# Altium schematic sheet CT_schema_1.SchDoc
size 451 x 258 mm
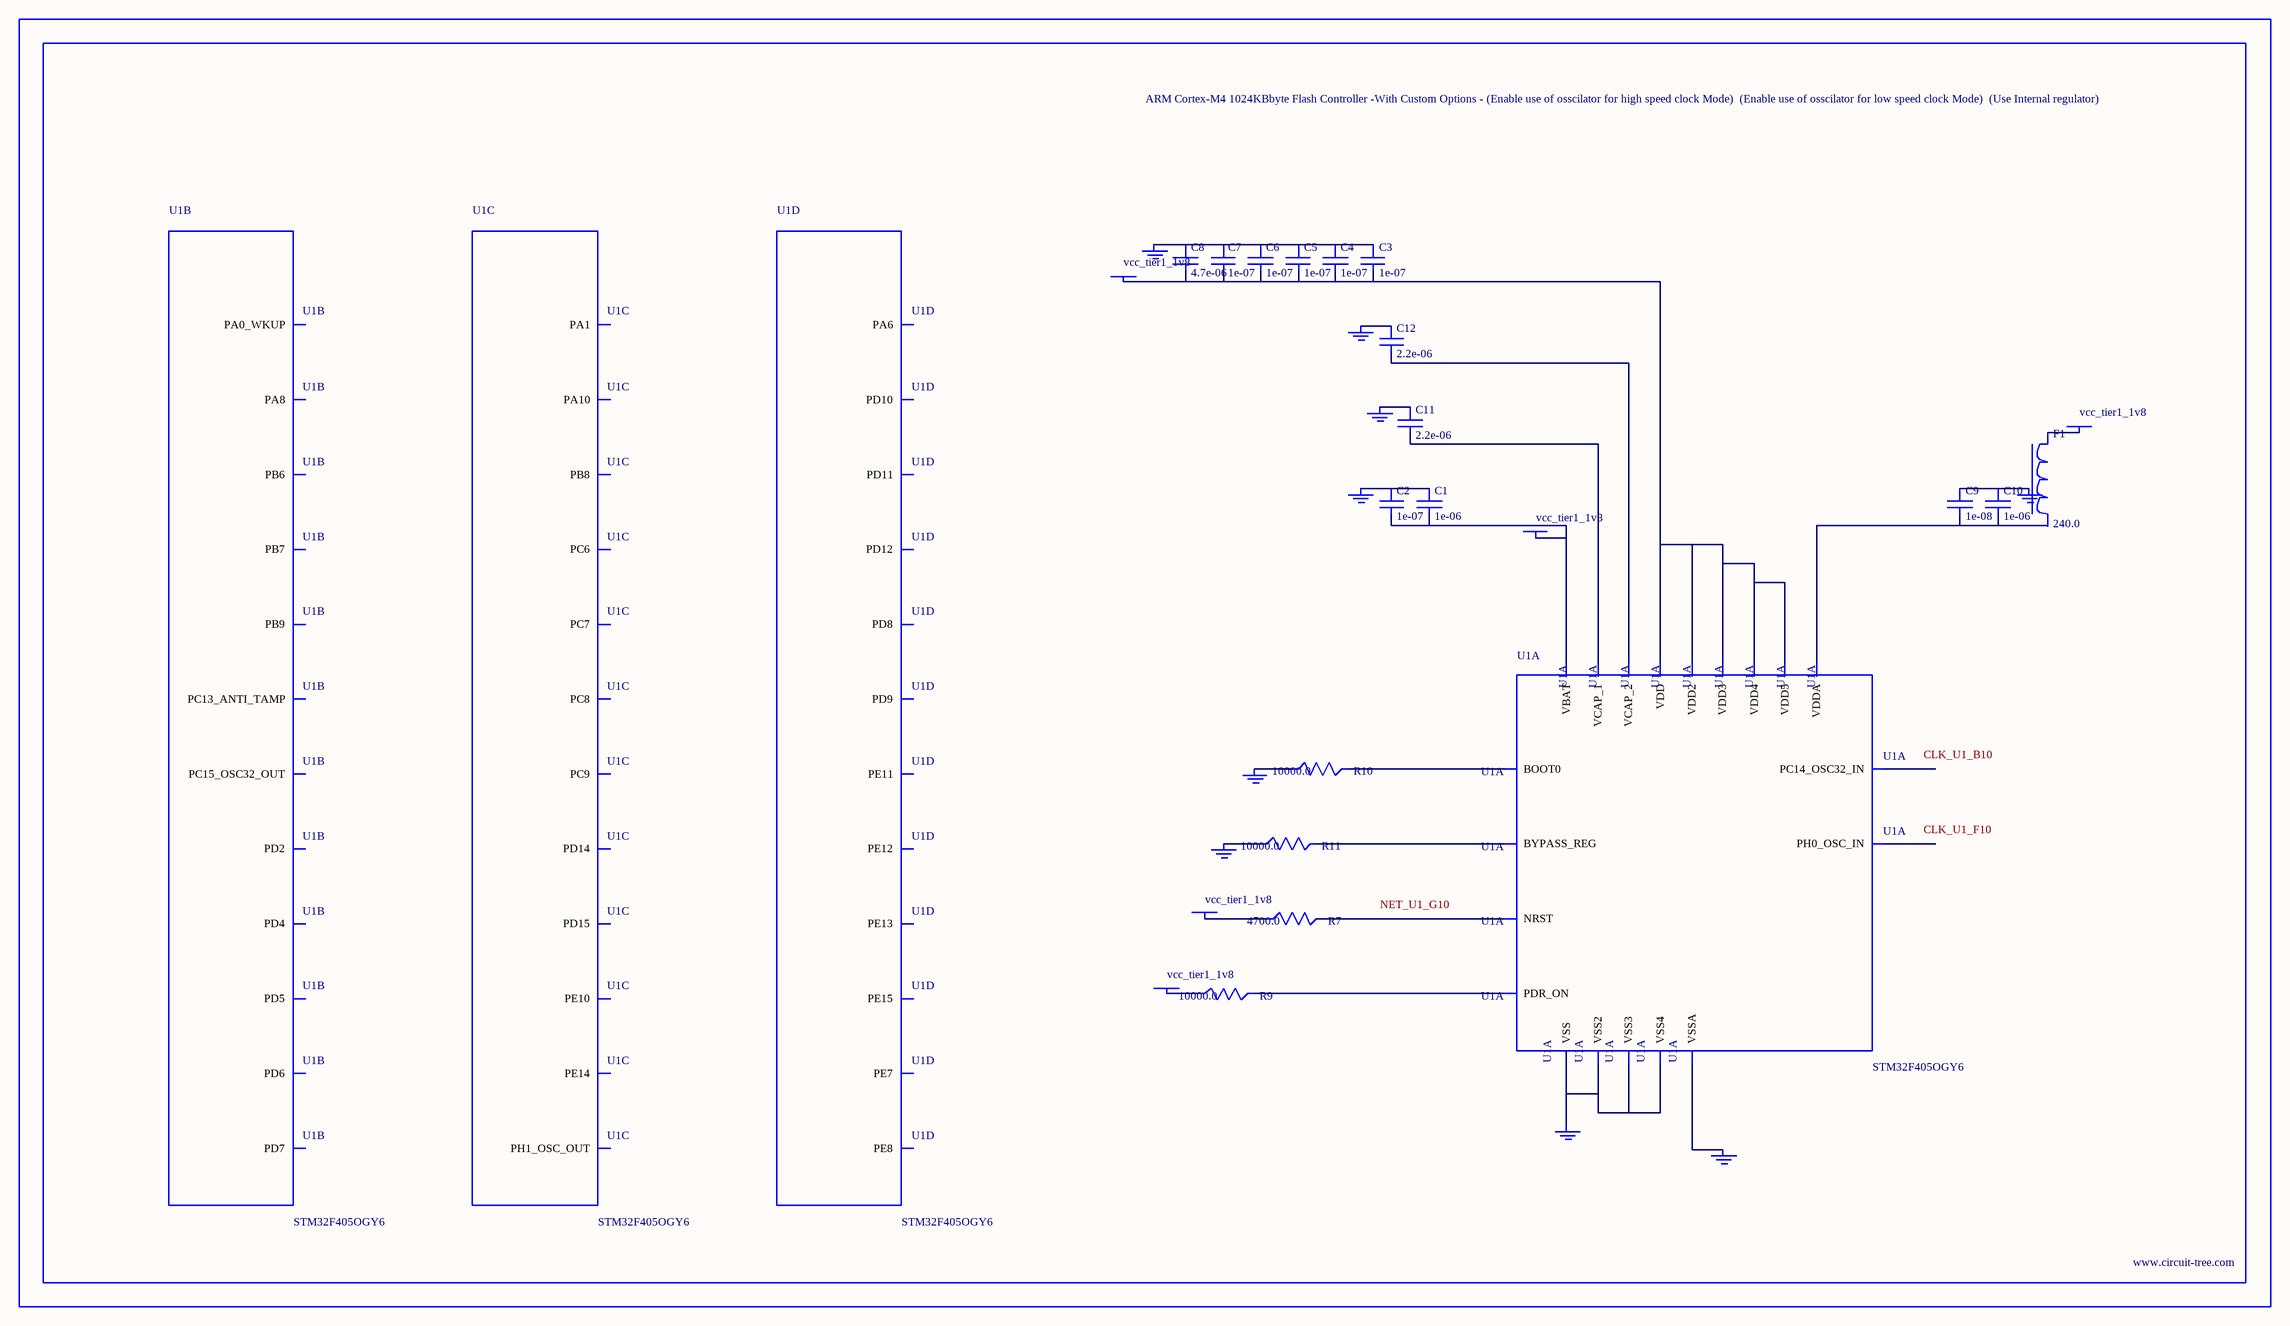
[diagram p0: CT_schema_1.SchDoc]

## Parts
BORDER0  (no value)
C1  1e-06  [C0603]
C2  1e-07  [C0603]
C3  1e-07  [C0603]
C4  1e-07  [C0603]
C5  1e-07  [C0603]
C6  1e-07  [C0603]
C7  1e-07  [C0603]
C8  4.7e-06  [C0603]
C9  1e-08  [C0603]
C10  1e-06  [C0603]
C11  2.2e-06  [C0603]
C12  2.2e-06  [C0603]
F1  240.0  [L0603]
GND_INSTANCE_0_0  (no value)
GND_INSTANCE_0_1  (no value)
GND_INSTANCE_0_2  (no value)
GND_INSTANCE_0_3  (no value)
GND_INSTANCE_0_4  (no value)
GND_INSTANCE_0_5  (no value)
GND_INSTANCE_0_6  (no value)
GND_INSTANCE_0_7  (no value)
GND_INSTANCE_0_8  (no value)
POWER_INSTANCE_0_0  vcc_tier1_1v8
POWER_INSTANCE_0_1  vcc_tier1_1v8
POWER_INSTANCE_0_2  vcc_tier1_1v8
POWER_INSTANCE_0_3  vcc_tier1_1v8
POWER_INSTANCE_0_4  vcc_tier1_1v8
R7  4700.0  [R0603]
R9  10000.0  [R0603]
R10  10000.0  [R0603]
R11  10000.0  [R0603]
U1  STM32F405OGY6  [WLCSP90]  (parts A,B,C,D of 9)

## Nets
NetC1_1: C1.1 C2.1 GND_INSTANCE_0_0.0(GND)
NetC1_2: C1.2 C2.2 POWER_INSTANCE_0_0.0(PWR) U1.A10(VBAT)
NetC3_1: C3.1 C4.1 C5.1 C6.1 C7.1 C8.1 GND_INSTANCE_0_2.0(GND)
NetC3_2: C3.2 C4.2 C5.2 C6.2 C7.2 C8.2 POWER_INSTANCE_0_2.0(PWR) U1.A1(VDD) U1.B8(VDD2) U1.E4(VDD3) U1.E6(VDD4) U1.F7(VDD5)
NetC9_1: C9.1 C10.1 GND_INSTANCE_0_1.0(GND)
NetC9_2: C9.2 C10.2 U1.G9(VDDA)
NetC11_1: C11.1 GND_INSTANCE_0_5.0(GND)
NetC11_2: C11.2 U1.F4(VCAP_1)
NetC12_1: C12.1 GND_INSTANCE_0_6.0(GND)
NetC12_2: C12.2 U1.B1(VCAP_2)
NetF1_1: F1.1 POWER_INSTANCE_0_1.0(PWR)
NetGND_INSTANCE_0_3_0: GND_INSTANCE_0_3.0(GND) R10.1
NetGND_INSTANCE_0_4_0: GND_INSTANCE_0_4.0(GND) R11.1
NetGND_INSTANCE_0_7_0: GND_INSTANCE_0_7.0(GND) U1.H10(VSSA)
NetGND_INSTANCE_0_8_0: GND_INSTANCE_0_8.0(GND) U1.C9(VSS) U1.E5(VSS2) U1.E7(VSS3) U1.E8(VSS4)
NetPOWER_INSTANCE_0_3_0: POWER_INSTANCE_0_3.0(PWR) R9.1
NetPOWER_INSTANCE_0_4_0: POWER_INSTANCE_0_4.0(PWR) R7.1
NetR7_2: R7.2 U1.G10(NRST)
NetR9_2: R9.2 U1.A8(PDR_ON)
NetR10_2: R10.2 U1.A7(BOOT0)
NetR11_2: R11.2 U1.D9(BYPASS_REG)

Not connected (* = marked no-connect by the designer): F1 2; U1 A4(PD4) A5(PD7) A9(PC13_ANTI_TAMP) B4(PD2) B5(PD6) B7(PB7) B9(PC15_OSC32_OUT) B10(PC14_OSC32_IN) C6(PD5) C7(PB6) C8(PB9) C10(PA0_WKUP) D1(PA8) D3(PA10) D8(PB8) E1(PC7) E2(PC8) E3(PC9) F1(PD15) F2(PD14) F3(PC6) F5(PE14) F6(PE10) F8(PA1) F9(PH1_OSC_OUT) F10(PH0_OSC_IN) G1(PD11) G2(PD12) G3(PD10) G4(PE15) G5(PE13) G6(PE7) H2(PD8) H3(PD9) H5(PE12) H6(PE8) H8(PA6) J5(PE11)

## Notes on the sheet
- Labels drawn without touching a wire or pin: CLK_U1_B10, CLK_U1_F10, NET_U1_G10

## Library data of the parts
BORDER0 = BORDER_PAGE0
C1 C10 = C0603C105K3RACTU
C2-C7 = 06035C104K4Z2A
C8 = GRM188R6YA475KE15D
C9 = 06035C103K4Z2A
C11 C12 = C0603C225K8RACTU
F1 = Z0603C241ASMST
GND_INSTANCE_0_0-GND_INSTANCE_0_8 = GND
POWER_INSTANCE_0_0-POWER_INSTANCE_0_4 = PWR
R7 = RC0603JR-074K7L
R9-R11 = RC0603JR-0710KL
